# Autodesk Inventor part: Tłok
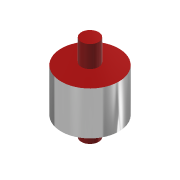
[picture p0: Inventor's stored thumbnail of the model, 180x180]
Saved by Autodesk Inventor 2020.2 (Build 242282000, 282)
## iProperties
Created: 2005-10
Part Number: Tłok
Document SubType Name: Modeling
Designer: F.Stasiak
Density: 1 g/cm^3
Material: Ogólny
Appearance: Gładkie — czerwone
Manager: www.cadconsulting.pl
Company: Fabian Stasiak CAD Consulting
Author: F.Stasiak
Subject: Zbiór ćwiczeń. Autodesk Inventor 2020. Kurs podstawowy
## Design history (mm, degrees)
sketch "Szkic1"
  geometry: C1 r 10 at (0, 0); 1 further point
  constraints: 1 centre point, 1 coincident
  dimensions: "d0" = 20 diameter of C1
extrude "Wyciągnięcie proste1" new body sketch "Szkic1" distance "d1" = 100; taper "d2" = 0 deg
node "Płaszczyzna konstrukcyjna1"
sketch "Szkic2"
  geometry: C1 r 10 at (0, 0) reference; C2 r 33.25 at (3, -3)
  constraints: 1 centre point
  dimensions: "d11" = 3 horizontal distance of C2.centre C1.centre; "d12" = 3 horizontal distance of C1.centre C2.centre (= d11); "d13" = 66.5 diameter of C2
extrude "Wyciągnięcie proste2" join sketch "Szkic2" stored distance "d7" = 50; taper "d8" = 0 deg
sketch "Szkic3"
  geometry: C1 r 3.998 at (-17.329, -17.779)
  constraints: 1 centre point
extrude "Wyciągnięcie proste3" cut sketch "Szkic3" distance "d9" = 5; taper "d10" = 0 deg
node "Bryła1"
node "Korpusy bryłowe"
node "Korpusy powierzchniowe"
